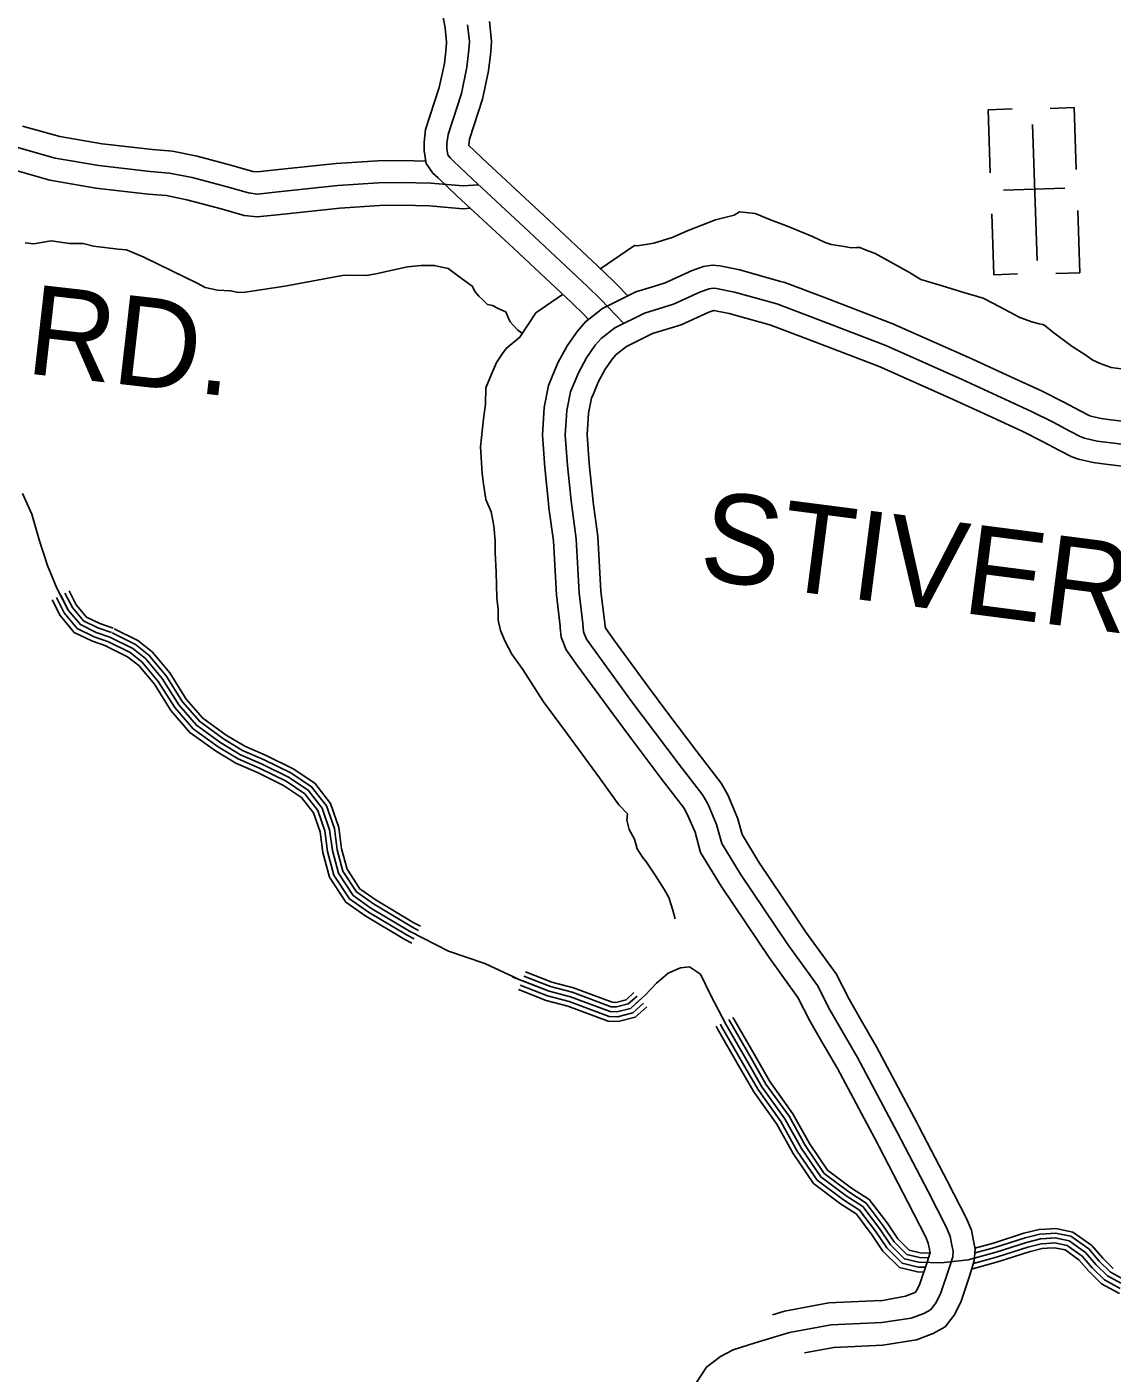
# Model space of a CAD drawing. Extents: x 1551132 to 1791609, y 378168 to 563823.
# Drawn here: x 1649438 to 1653929, y 400926 to 406494 of the extents above; entities that cross this region are included whole.
import ezdxf

# ---------------------------------------------------------------- set-up
doc = ezdxf.new("R2010")
doc.units = 0
for name, color, linetype in [('DESIGN - ROW - Right-of-Way and Easement Labels', 7, 'Continuous'), ('DESIGN - TRANSPORTATION - Text', 7, 'Continuous'), ('DESIGN - UTILITIES - Cable (Underground) with Text', 7, 'Continuous'), ('SURVEY - DRAINAGE - Natural Features', 7, 'Continuous'), ('SURVEY - PROPERTY - Owners', 7, 'Continuous')]:
    doc.layers.add(name, color=color, linetype=linetype)

msp = doc.modelspace()

# ---------------------------------------------------------------- linework, layer by layer
at = {"layer": 'DESIGN - TRANSPORTATION - Text'}
for points in [[(1651808.948, 405492.207), (1651951.911, 405590.101), (1651964.761, 405587.868), (1652032.826, 405599.401), (1652108.982, 405622.902), (1652175.172, 405652.478), (1652287.453, 405695.754), (1652365.576, 405715.23), (1652387.667, 405729.097), (1652413.65, 405726.913), (1652451.624, 405722.638), (1652515.448, 405696.146), (1652581.288, 405671.637), (1652688.985, 405626.803), (1652740.826, 405602.394), (1652766.767, 405594.193), (1652820.716, 405585.801), (1652850.673, 405579.576), (1652870.681, 405581.443), (1652884.681, 405581.343), (1652910.613, 405571.143), (1652948.521, 405556.851), (1653089.993, 405477.715), (1653137.808, 405449.331), (1653211.656, 405426.773), (1653315.454, 405395.988), (1653395.285, 405371.388), (1653435.151, 405351.071), (1653484.983, 405324.678), (1653546.765, 405292.186), (1653596.639, 405273.802), (1653626.588, 405265.577), (1653642.571, 405263.46), (1653650.546, 405259.393), (1653682.37, 405233.126), (1653763.977, 405172.449), (1653811.775, 405142.065), (1653849.6, 405115.756), (1653879.507, 405101.514), (1653925.398, 405085.164), (1653987.338, 405076.714)], [(1649430.303, 405601.267), (1649466.277, 405597), (1649538.351, 405608.509), (1649614.282, 405597.958), (1649670.273, 405597.558), (1649714.205, 405587.233), (1649816.119, 405574.491), (1649850.102, 405572.241), (1649921.9, 405541.69), (1650037.522, 405484.772), (1650143.186, 405433.946), (1650175.069, 405415.687), (1650226.993, 405405.304), (1650280.975, 405402.92), (1650312.924, 405394.678), (1650340.932, 405396.487), (1650505.095, 405421.363), (1650751.389, 405467.697), (1650843.362, 405465.039), (1650881.411, 405472.781), (1651013.599, 405501.898), (1651067.64, 405507.523), (1651123.63, 405507.124), (1651181.546, 405494.69), (1651235.278, 405454.247), (1651281.068, 405421.871), (1651292.91, 405397.746), (1651308.792, 405379.604), (1651324.7, 405365.47), (1651344.567, 405345.294), (1651364.533, 405341.153), (1651388.457, 405328.961), (1651412.39, 405318.777), (1651420.365, 405314.71), (1651434.148, 405282.559), (1651438.098, 405274.518), (1651450.006, 405260.409), (1651469.872, 405240.242), (1651488.297, 405225.508)], [(1651544.754, 405311.31), (1651655.059, 405386.837)], [(1651544.754, 405311.31), (1651477.988, 405210.974), (1651421.673, 405163.29), (1651405.548, 405143.372), (1651381.299, 405105.48), (1651360.983, 405057.553), (1651336.617, 405001.627), (1651336.175, 404933.525), (1651327.783, 404873.482), (1651315.017, 404757.387), (1651322.3, 404647.159), (1651326.075, 404613.075), (1651337.591, 404538.873), (1651359.257, 404488.638), (1651370.874, 404430.462), (1651376.474, 404368.319), (1651376.157, 404320.242), (1651379.632, 404240.09), (1651382.923, 404131.887), (1651388.607, 404083.769), (1651388.315, 404039.702), (1651398.04, 403997.559), (1651417.739, 403951.349), (1651445.397, 403899.065), (1651490.987, 403836.646), (1651576.102, 403701.818), (1651675.225, 403568.906), (1651808.03, 403387.668), (1651887.303, 403276.923), (1651923.052, 403238.614), (1651920.885, 403212.58), (1651930.635, 403174.454), (1651952.368, 403134.236), (1651964.101, 403094.085), (1651985.875, 403059.876), (1652001.75, 403039.734), (1652037.391, 402985.391), (1652076.99, 402925.014), (1652094.781, 402892.83), (1652110.439, 402840.637), (1652121.314, 402804.611)]]:
    msp.add_lwpolyline(points, dxfattribs=at)
at = {"layer": 'DESIGN - UTILITIES - Cable (Underground) with Text'}
for p, q in [((1653415.718, 406151.579), (1653424.829, 405890.873)), ((1653515.337, 406155.055), (1653416.334, 406151.579)), ((1653771.993, 406160.034), (1653672.332, 406156.549)), ((1653780.887, 405903.461), (1653771.909, 406160.034)), ((1653733.495, 405827.342), (1653480.006, 405818.489)), ((1653430.773, 405720.061), (1653439.576, 405468.73)), ((1653795.768, 405477.226), (1653786.739, 405735.157)), ((1653439.709, 405468.73), (1653537.92, 405472.156)), ((1653795.593, 405477.226), (1653696.19, 405473.742))]:
    msp.add_line(p, q, dxfattribs=at)
msp.add_lwpolyline([(1653598.898, 406090.505), (1653618.571, 405527.825)], dxfattribs=at)
at = {"layer": 'SURVEY - DRAINAGE - Natural Features'}
for points in [[(1649419.67, 404564.306), (1649458.777, 404478.912), (1649489.126, 404371.768), (1649523.55, 404266.49), (1649562.383, 404173.096), (1649609.282, 404081.443), (1649659.272, 404021.742), (1649724.212, 403989.616), (1649781.569, 403969.749)], [(1649419.67, 404564.306), (1649458.777, 404478.912), (1649489.126, 404371.768), (1649523.55, 404266.49), (1649562.383, 404173.096), (1649609.282, 404081.443), (1649659.272, 404021.742), (1649724.212, 403989.616), (1649781.569, 403969.749)], [(1649542.15, 404124.82), (1649575.724, 404059.21), (1649634.006, 403989.616), (1649708.737, 403952.64), (1649768.478, 403931.948)], [(1649559.958, 404133.936), (1649592.507, 404070.326), (1649646.639, 404005.675), (1649716.479, 403971.132), (1649775.028, 403950.848)], [(1649577.757, 404143.045), (1649609.282, 404081.443), (1649659.272, 404021.742), (1649724.212, 403989.616), (1649781.569, 403969.749)], [(1649595.557, 404152.154), (1649626.056, 404092.56), (1649671.905, 404037.809), (1649731.945, 404008.1), (1649788.111, 403988.649)], [(1649612.473, 404160.812), (1649641.997, 404103.119), (1649683.913, 404053.068), (1649739.303, 404025.667), (1649794.336, 404006.6)], [(1649781.569, 403969.749), (1649876.017, 403922.656), (1649928.624, 403880.905), (1649997.856, 403798.553), (1650066.196, 403690.183), (1650139.352, 403605.706), (1650240.908, 403532.338), (1650321.29, 403483.686), (1650412.021, 403444.727), (1650520.252, 403391.176), (1650602.433, 403336.458), (1650659.94, 403262.497), (1650690.914, 403173.362), (1650701.964, 403086.86), (1650726.805, 402993.915), (1650787.695, 402901.813), (1650861.952, 402849.353), (1651020.789, 402754.118), (1651182.044, 402670.824), (1651332.399, 402619.939), (1651472.279, 402555.354), (1651448.563, 402564.129), (1651598.642, 402505.236), (1651687.915, 402482.344), (1651851.92, 402421.001), (1651879.903, 402420.109), (1651936.426, 402434.326), (1651996.308, 402488.503), (1652044.065, 402539.062), (1652091.481, 402579.614), (1652142.28, 402602.031), (1652180.471, 402606.814), (1652225.42, 402575.33), (1652268.452, 402487.803), (1652330.45, 402369.625), (1652417.348, 402218.596), (1652479.688, 402110.426), (1652575.194, 401977.148), (1652643.051, 401854.778), (1652723.116, 401738.025), (1652828.463, 401658.523), (1652896.987, 401614.264), (1652965.943, 401523.903), (1653011.667, 401456.334), (1653069.716, 401398.383), (1653129.281, 401384.449), (1653221.237, 401381.508), (1653333.726, 401393.933), (1653448.907, 401426.309), (1653574.354, 401466.368), (1653632.869, 401480.527), (1653693.043, 401484.611), (1653750.675, 401472.744), (1653819.065, 401424.484), (1653861.406, 401375.049), (1653909.804, 401327.415), (1653964.82, 401297.614)], [(1649781.569, 403969.749), (1649876.017, 403922.656), (1649928.624, 403880.905), (1649997.856, 403798.553), (1650066.196, 403690.183), (1650139.352, 403605.706), (1650240.908, 403532.338), (1650321.29, 403483.686), (1650412.021, 403444.727), (1650520.252, 403391.176), (1650602.433, 403336.458), (1650659.94, 403262.497), (1650690.914, 403173.362), (1650701.964, 403086.86), (1650726.805, 402993.915), (1650787.695, 402901.813), (1650861.952, 402849.353), (1651020.789, 402754.118), (1651182.044, 402670.824), (1651332.399, 402619.939), (1651472.279, 402555.354), (1651448.563, 402564.129), (1651598.642, 402505.236), (1651687.915, 402482.344), (1651851.92, 402421.001), (1651879.903, 402420.109), (1651936.426, 402434.326), (1651996.308, 402488.503), (1652044.065, 402539.062), (1652091.481, 402579.614), (1652142.28, 402602.031), (1652180.471, 402606.814), (1652225.42, 402575.33), (1652268.452, 402487.803), (1652330.45, 402369.625), (1652417.348, 402218.596), (1652479.688, 402110.426), (1652575.194, 401977.148), (1652643.051, 401854.778), (1652723.116, 401738.025), (1652828.463, 401658.523), (1652896.987, 401614.264), (1652965.943, 401523.903), (1653011.667, 401456.334), (1653069.716, 401398.383), (1653129.281, 401384.449), (1653221.237, 401381.508), (1653333.726, 401393.933), (1653448.907, 401426.309), (1653574.354, 401466.368), (1653632.869, 401480.527), (1653693.043, 401484.611), (1653750.675, 401472.744), (1653819.065, 401424.484), (1653861.406, 401375.049), (1653909.804, 401327.415), (1653964.82, 401297.614)], [(1649781.569, 403969.749), (1649876.017, 403922.656), (1649928.624, 403880.905), (1649997.856, 403798.553), (1650066.196, 403690.183), (1650139.352, 403605.706), (1650240.908, 403532.338), (1650321.29, 403483.686), (1650412.021, 403444.727), (1650520.252, 403391.176), (1650602.433, 403336.458), (1650659.94, 403262.497), (1650690.914, 403173.362), (1650701.964, 403086.86), (1650726.805, 402993.915), (1650787.695, 402901.813), (1650861.952, 402849.353), (1651020.789, 402754.118), (1651049.564, 402739.259)], [(1649790.494, 403987.649), (1649886.808, 403939.623), (1649942.632, 403895.322), (1650014.047, 403810.378), (1650082.304, 403702.134), (1650152.952, 403620.557), (1650251.958, 403549.03), (1650330.456, 403501.52), (1650420.404, 403462.894), (1650530.268, 403408.535), (1650616.224, 403351.3), (1650677.748, 403272.173), (1650710.489, 403177.962), (1650721.63, 403090.726), (1650745.288, 403002.224), (1650802.303, 402915.98), (1650872.876, 402866.12), (1651030.531, 402771.601), (1651058.739, 402757.026)], [(1649798.969, 404004.65), (1649897.066, 403955.74), (1649955.948, 403909.014), (1650029.422, 403821.612), (1650097.612, 403713.484), (1650165.868, 403634.665), (1650262.458, 403564.88), (1650339.164, 403518.454), (1650428.37, 403480.153), (1650539.784, 403425.027), (1650629.324, 403365.408), (1650694.672, 403281.365), (1650729.088, 403182.329), (1650740.313, 403094.401), (1650762.837, 403010.124), (1650816.186, 402929.439), (1650883.259, 402882.054), (1651039.781, 402788.202), (1651067.455, 402773.91)], [(1649763.72, 403933.948), (1649854.426, 403888.722), (1649900.6, 403852.079), (1649965.481, 403774.902), (1650033.98, 403666.283), (1650112.161, 403576.005), (1650218.809, 403498.962), (1650302.957, 403448.027), (1650395.246, 403408.393), (1650500.219, 403356.458), (1650574.85, 403306.765), (1650624.316, 403243.147), (1650651.765, 403164.162), (1650662.631, 403079.126), (1650689.847, 402977.29), (1650758.479, 402873.479), (1650840.094, 402815.819), (1651001.307, 402719.158), (1651031.214, 402703.716)], [(1649772.644, 403951.848), (1649865.225, 403905.689), (1649914.616, 403866.488), (1649981.664, 403786.728), (1650050.088, 403678.233), (1650125.753, 403590.856), (1650229.858, 403515.646), (1650312.123, 403465.853), (1650403.638, 403426.56), (1650510.235, 403373.817), (1650588.642, 403321.616), (1650642.132, 403252.822), (1650671.34, 403168.762), (1650682.298, 403082.993), (1650708.322, 402985.607), (1650773.087, 402887.646), (1650851.027, 402832.586), (1651011.048, 402736.634), (1651040.389, 402721.492)], [(1651493.837, 402567.846), (1651604.801, 402524.304), (1651693.915, 402501.453), (1651855.845, 402440.885), (1651877.744, 402440.185), (1651926.71, 402452.502), (1651963.067, 402485.394)], [(1651500.77, 402585.538), (1651610.651, 402542.421), (1651699.623, 402519.603), (1651859.57, 402459.777), (1651875.686, 402459.26), (1651917.477, 402469.777), (1651950.326, 402499.486)], [(1651471.92, 402511.995), (1651586.326, 402467.102), (1651675.907, 402444.126), (1651844.07, 402381.233), (1651884.227, 402379.95), (1651955.859, 402397.967), (1652003.316, 402440.893)], [(1651479.22, 402530.612), (1651592.484, 402486.169), (1651681.916, 402463.235), (1651847.995, 402401.117), (1651882.061, 402400.034), (1651946.143, 402416.151), (1651989.9, 402455.727)], [(1651486.528, 402549.229), (1651598.642, 402505.236), (1651687.915, 402482.344), (1651851.92, 402421.001), (1651879.903, 402420.109), (1651936.426, 402434.326), (1651976.484, 402470.561)], [(1652290.126, 402360.383), (1652295.393, 402350.349), (1652382.682, 402198.637), (1652446.022, 402088.734), (1652541.337, 401955.731), (1652608.993, 401833.719), (1652693.816, 401710.024), (1652805.539, 401625.714), (1652869.421, 401584.446), (1652933.452, 401500.544), (1652980.693, 401430.734), (1653049.516, 401362.024), (1653124.031, 401344.598), (1653149.047, 401343.798)], [(1652307.834, 402369.675), (1652312.926, 402359.983), (1652400.015, 402208.612), (1652462.855, 402099.584), (1652558.261, 401966.439), (1652626.018, 401844.253), (1652708.466, 401724.025), (1652816.997, 401642.114), (1652883.204, 401599.355), (1652949.702, 401512.219), (1652996.176, 401443.534), (1653059.616, 401380.207), (1653126.656, 401364.524), (1653155.947, 401363.59)], [(1652325.542, 402378.975), (1652330.45, 402369.625), (1652417.348, 402218.596), (1652479.688, 402110.426), (1652575.194, 401977.148), (1652643.051, 401854.778), (1652723.116, 401738.025), (1652828.463, 401658.523), (1652896.987, 401614.264), (1652965.943, 401523.903), (1653011.667, 401456.334), (1653069.716, 401398.383), (1653129.281, 401384.449), (1653162.03, 401383.399)], [(1652343.25, 402388.275), (1652347.975, 402379.267), (1652434.681, 402228.579), (1652496.521, 402121.268), (1652592.127, 401987.857), (1652660.084, 401865.303), (1652737.765, 401752.025), (1652839.93, 401674.932), (1652910.77, 401629.172), (1652982.185, 401535.587), (1653027.159, 401469.135), (1653079.816, 401416.558), (1653131.906, 401404.375), (1653168.539, 401403.2)], [(1652360.075, 402397.101), (1652364.633, 402388.425), (1652451.147, 402238.063), (1652512.513, 402131.577), (1652608.21, 401998.032), (1652676.259, 401875.312), (1652751.682, 401765.326), (1652850.821, 401690.516), (1652923.861, 401643.331), (1652997.618, 401546.678), (1653041.867, 401481.293), (1653089.407, 401433.834), (1653134.398, 401423.309), (1653175.013, 401422.009)], [(1653360.992, 401442.101), (1653437.699, 401463.668), (1653563.821, 401503.944), (1653626.92, 401519.211), (1653654.352, 401521.07)], [(1653654.344, 401521.07), (1653695.701, 401523.878), (1653766.508, 401509.303), (1653845.523, 401453.551), (1653889.947, 401401.683), (1653933.229, 401359.082)], [(1653355.734, 401379.341), (1653454.657, 401407.15), (1653579.754, 401447.101), (1653635.919, 401460.685), (1653658.335, 401462.202)], [(1653358.592, 401400.925), (1653448.907, 401426.309), (1653574.354, 401466.368), (1653632.869, 401480.527), (1653656.985, 401482.16)], [(1653361.692, 401422.567), (1653443.157, 401445.468), (1653568.954, 401485.636), (1653629.819, 401500.369), (1653655.636, 401502.119)], [(1653655.627, 401502.111), (1653694.41, 401504.753), (1653758.8, 401491.494), (1653832.631, 401439.384), (1653876.039, 401388.708), (1653921.821, 401343.657), (1653967.345, 401318.998)], [(1653656.985, 401482.16), (1653693.043, 401484.611), (1653750.675, 401472.744), (1653819.065, 401424.484), (1653861.406, 401375.049), (1653909.804, 401327.415), (1653964.82, 401297.614)], [(1653658.344, 401462.21), (1653691.676, 401464.468), (1653742.55, 401453.993), (1653805.499, 401409.584), (1653846.773, 401361.391), (1653897.788, 401311.173), (1653962.295, 401276.23)], [(1653347.476, 401356.249), (1653460.407, 401387.991), (1653585.154, 401427.826), (1653638.969, 401440.851), (1653659.685, 401442.251)], [(1653659.694, 401442.251), (1653690.318, 401444.334), (1653734.434, 401435.251), (1653791.932, 401394.675), (1653832.131, 401347.732), (1653885.78, 401294.939), (1653959.778, 401254.855)]]:
    msp.add_lwpolyline(points, dxfattribs=at)
at = {"layer": 'SURVEY - PROPERTY - Owners'}
for points in [[(1651151.097, 406583.835), (1651168.513, 406489.533), (1651174.763, 406431.056), (1651173.221, 406407.589), (1651165.496, 406342.221), (1651144.647, 406243.343), (1651088.048, 406069.23), (1651082.148, 406016.77), (1651081.915, 405982.003), (1651090.34, 405929.018), (1651117.889, 405889.3), (1651139.688, 405869.775), (1651216.662, 405795.556), (1651451.489, 405579.109), (1651692.783, 405351.945), (1651744.874, 405300.96), (1651761.99, 405283.31)], [(1651261.886, 406503.125), (1651269.386, 406432.981), (1651267.144, 406398.955), (1651258.636, 406326.929), (1651235.87, 406218.967), (1651180.679, 406049.179), (1651176.404, 406011.162), (1651176.254, 405989.136), (1651180.079, 405965.077), (1651189.046, 405952.152), (1651203.887, 405938.86), (1651281.343, 405864.175), (1651515.754, 405648.111), (1651758.082, 405419.972), (1651811.697, 405367.495), (1651908.495, 405267.701)], [(1651351.709, 406516.2), (1651360.409, 406434.84), (1651357.5, 406390.647), (1651348.234, 406312.22), (1651323.626, 406195.517), (1651269.785, 406029.896), (1651267.077, 406005.77), (1651267.06, 406003.953), (1651343.567, 405930.185), (1651577.578, 405714.488), (1651820.897, 405485.415), (1651875.988, 405431.497), (1651924.911, 405381.062)], [(1649420.362, 406083.779), (1649574.492, 406040.062), (1649748.946, 406009.886), (1649957.116, 405986.185), (1650041.122, 405979.652), (1650142.32, 405959.418), (1650291.392, 405919.351), (1650373.006, 405896.383), (1650392.306, 405894.042), (1650467.354, 405902.434), (1650717.64, 405928.801), (1650889.828, 405939.793), (1650989.817, 405941.118), (1651089.606, 405938.685)], [(1649394.688, 405996.769), (1649554.334, 405951.493), (1649736.071, 405920.059), (1649948.466, 405895.875), (1650028.673, 405889.633), (1650121.637, 405871.049), (1650267.334, 405831.89), (1650355.14, 405807.181), (1650391.864, 405802.714), (1650477.146, 405812.256), (1650725.281, 405838.39), (1650893.319, 405849.124), (1650989.309, 405850.391), (1651109.264, 405847.466), (1651243.153, 405836.432), (1651306.484, 405840.999)], [(1649368.005, 405906.325), (1649533.376, 405859.424), (1649722.688, 405826.681), (1649939.475, 405801.997), (1650015.731, 405796.064), (1650100.138, 405779.188), (1650242.326, 405740.971), (1650336.565, 405714.454), (1650391.406, 405707.778), (1650487.329, 405718.512), (1650733.231, 405744.413), (1650896.952, 405754.872), (1650988.784, 405756.08), (1651104.239, 405753.263), (1651242.669, 405741.855), (1651272.644, 405744.013)], [(1652971.56, 401225.228), (1653074.057, 401244.287), (1653109.673, 401257.696), (1653115.006, 401260.688), (1653117.956, 401264.471), (1653131.439, 401291.03), (1653163.28, 401384.758), (1653175.963, 401425.009), (1653175.322, 401427.7), (1653173.347, 401438.051), (1653168.414, 401463.793), (1653158.455, 401488.094), (1653083.474, 401633.097), (1652965.119, 401861.153), (1652957.477, 401875.895), (1652792.789, 402185.554), (1652728.399, 402296.356), (1652677.809, 402383.384), (1652628.71, 402479.636), (1652509.255, 402644.215), (1652463.664, 402712.142), (1652311.226, 402939.265), (1652226.17, 403079.135), (1652202.962, 403163.854), (1652172.204, 403235.406), (1652156.247, 403263.473), (1652062.849, 403385.576), (1651938.935, 403550.231), (1651862.187, 403652.217), (1651716.699, 403850.822), (1651670.05, 403917.257), (1651649.592, 403969.567), (1651645.259, 404008.868), (1651644.517, 404015.584), (1651629.109, 404144.43), (1651616.743, 404368.16), (1651598.569, 404504.222), (1651596.144, 404522.339), (1651580.894, 404671.477), (1651571.228, 404805.605), (1651578.761, 404919.975), (1651596.236, 405011.327), (1651611.594, 405047.987), (1651635.035, 405103.938), (1651673.684, 405175.34), (1651715.983, 405235.583), (1651749.457, 405274.118), (1651820.422, 405329.111), (1651958.036, 405397.838), (1652027.342, 405419.247), (1652079.891, 405435.472), (1652190.764, 405486.007), (1652237.629, 405502.249), (1652274.045, 405508.216), (1652305.411, 405505.324), (1652387.717, 405489.082), (1652556.688, 405441.539), (1652570.905, 405437.539), (1652742.434, 405372.663), (1653028.061, 405263.418), (1653036.777, 405259.56), (1653347.886, 405121.54), (1653494.116, 405054.096), (1653636.813, 404988.278), (1653729.136, 404942.218), (1653797.234, 404905.451), (1653834.108, 404886.634), (1653841.466, 404884.117), (1653883.749, 404874.008), (1653923.606, 404869.208), (1654038.595, 404855.358)], [(1652975.393, 401135.259), (1653097.49, 401152.351), (1653149.622, 401171.977), (1653177.722, 401187.777), (1653197.904, 401213.661), (1653218.554, 401254.329), (1653252.895, 401355.415), (1653269.261, 401407.358), (1653271.336, 401431.417), (1653267.553, 401447.418), (1653259.236, 401490.819), (1653244.12, 401527.703), (1653167.197, 401676.474), (1653040.95, 401919.747), (1652875.204, 402231.405), (1652760.624, 402428.535), (1652709.35, 402529.054), (1652586.578, 402698.2), (1652390.691, 402990.066), (1652313.609, 403116.82), (1652292.168, 403195.08), (1652256.761, 403277.457), (1652235.036, 403315.666), (1652137.964, 403442.57), (1651937.894, 403708.435), (1651793.322, 403905.79), (1651753.731, 403962.166), (1651741.948, 403992.292), (1651738.19, 404026.368), (1651723.09, 404152.638), (1651710.691, 404377.019), (1651689.8, 404533.373), (1651674.842, 404679.669), (1651665.742, 404805.897), (1651672.467, 404907.975), (1651687, 404983.96), (1651720.183, 405063.17), (1651753.999, 405125.63), (1651790.356, 405177.415), (1651814.547, 405205.266), (1651870.846, 405248.892), (1651993.251, 405310.027), (1652113.49, 405347.161), (1652225.829, 405398.363), (1652260.862, 405410.505), (1652277.387, 405413.213), (1652291.911, 405411.872), (1652365.793, 405397.296), (1652541.405, 405347.887), (1652708.918, 405284.527), (1652992.086, 405176.224), (1653309.021, 405035.621), (1653596.014, 404903.259), (1653685.678, 404858.524), (1653753.402, 404821.957), (1653797.234, 404799.59), (1653815.192, 404793.448), (1653867.091, 404781.039), (1654026.92, 404761.789)], [(1652979.793, 401040.682), (1653120.031, 401063.907), (1653188.055, 401089.517), (1653238.053, 401117.634), (1653274.819, 401164.785), (1653302.36, 401219.028), (1653339.101, 401327.19), (1653358.776, 401389.616), (1653362.959, 401438.126), (1653356.276, 401466.385), (1653355.043, 401472.843), (1653346.609, 401516.82), (1653326.535, 401565.813), (1653247.737, 401718.2), (1653129.331, 401946.356), (1653121.257, 401961.931), (1652954.486, 402275.506), (1652888.337, 402389.326), (1652840.297, 402471.969), (1652786.923, 402576.597), (1652660.968, 402750.135), (1652617.269, 402815.245), (1652467.139, 403038.934), (1652397.724, 403153.071), (1652379.9, 403218.147), (1652377.991, 403225.106), (1652338.101, 403317.908), (1652310.835, 403365.876), (1652210.22, 403497.404), (1652086.748, 403661.475), (1652010.717, 403762.511), (1651867.029, 403958.666), (1651834.229, 404005.368), (1651830.796, 404014.16), (1651829.138, 404029.177), (1651828.305, 404036.743), (1651813.497, 404160.538), (1651801.064, 404385.544), (1651781.931, 404528.715), (1651779.889, 404543.99), (1651765.215, 404687.544), (1651756.665, 404806.18), (1651762.607, 404896.433), (1651774.315, 404957.634), (1651782.223, 404976.502), (1651802.097, 405023.953), (1651831.255, 405077.813), (1651861.904, 405121.464), (1651877.171, 405139.031), (1651919.353, 405171.723), (1652027.126, 405225.55), (1652081.933, 405242.484), (1652145.815, 405262.209), (1652259.562, 405314.052), (1652281.153, 405321.536), (1652344.702, 405309.002), (1652506.589, 405263.451), (1652513.023, 405261.643), (1652676.669, 405199.741), (1652957.479, 405092.339), (1652961.779, 405090.439), (1653271.638, 404952.968), (1653416.635, 404886.1), (1653556.765, 404821.465), (1653643.871, 404778.006), (1653711.236, 404741.638), (1653761.768, 404715.854), (1653789.909, 404706.221), (1653851.066, 404691.603), (1653901.481, 404685.528), (1654015.687, 404671.778)], [(1652971.218, 401225.87), (1652756.031, 401215.961), (1652572.586, 401181.785), (1652523.395, 401167.127)], [(1652975.393, 401135.259), (1652766.473, 401125.634), (1652593.902, 401093.483), (1652451.28, 401050.973), (1652360.866, 401021.914), (1652308.517, 400994.439), (1652250.001, 400950.987), (1652209.311, 400887.294), (1652174.603, 400821.534)], [(1652979.734, 401041.065), (1652777.331, 401031.74), (1652655.534, 401009.047)]]:
    msp.add_lwpolyline(points, dxfattribs=at)

# ---------------------------------------------------------------- texts
at = {"layer": 'DESIGN - ROW - Right-of-Way and Easement Labels'}
for s, height, rotation, p in [('RD.', 369.9915, 353.504136, (1649428.368, 405061.579)), ('STIVERSVILLE', 369.9916, 352.642292, (1652211.569, 404212.042))]:
    msp.add_text(s, height=height, rotation=rotation, dxfattribs=at).set_placement(p)

doc.saveas('drawing.dxf')
